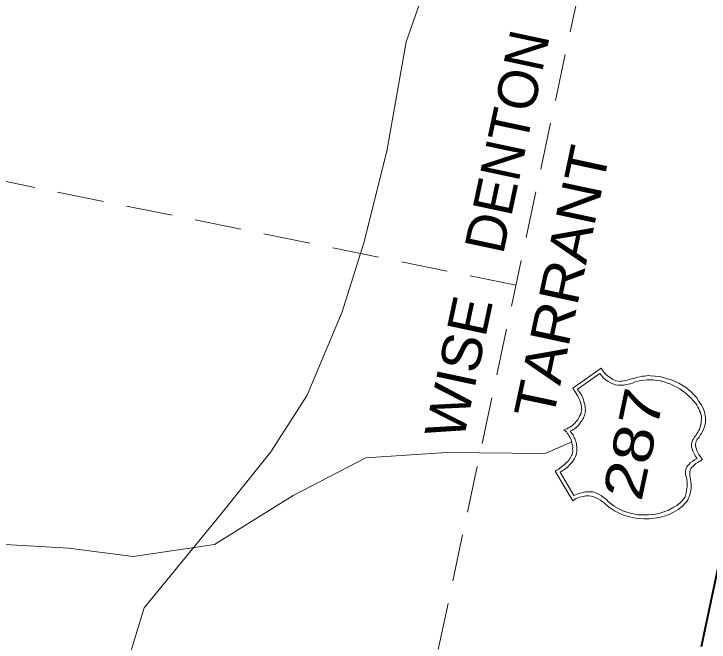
# Model space of a CAD drawing. Extents: x 2363411 to 2369126, y 6976878 to 6988319.
# Drawn here: x 2368067.8 to 2368157, y 6987951.6 to 6988032.2 of the extents above; entities that cross this region are included whole.
import ezdxf

# ---------------------------------------------------------------- set-up
doc = ezdxf.new("R2010")
doc.units = 0
doc.header["$LTSCALE"] = 2
doc.linetypes.add('LONG_DASHED', pattern=[7.5, 6, -1.5])
doc.linetypes.add('MEDIUM_DASHED', pattern=[4.5, 3, -1.5])
doc.layers.add('62', color=7, linetype='Continuous', lineweight=13)
doc.layers.add('63', color=7, linetype='Continuous', lineweight=13)

msp = doc.modelspace()

# ---------------------------------------------------------------- linework, layer by layer
at = {"layer": '62', "linetype": 'MEDIUM_DASHED'}
for p, q in [((2368191.192, 6988273.413), (2368097.525, 6987835.044)), ((2368132.221, 6987997.421), (2368039.262, 6988016.273))]:
    msp.add_line(p, q, dxfattribs=at)
at = {"layer": '62'}
msp.add_line((2368135.935, 6987975.828), (2368139.379, 6987977.301), dxfattribs=at)
for points in [[(2368072.165, 6987905.558), (2368069.558, 6987916.954), (2368070.74, 6987931.312), (2368081.321, 6987945.504), (2368084.53, 6987956.002), (2368094.219, 6987967.853), (2368100.778, 6987976.045), (2368105.415, 6987983.319), (2368109.901, 6987993.976), (2368112.685, 6988002.816), (2368115.664, 6988014.605), (2368118.107, 6988028.624), (2368124.138, 6988045.861), (2368127.394, 6988057.221), (2368131.763, 6988070.025), (2368141.291, 6988083.154), (2368150.678, 6988095.548), (2368159.881, 6988106.746), (2368173.939, 6988118.699), (2368182.972, 6988126.824), (2368192.837, 6988137.028), (2368200.988, 6988142.326)], [(2368139.487, 6987969.731), (2368137.22, 6987973.553), (2368137.457, 6987973.685), (2368137.692, 6987973.82), (2368137.889, 6987973.987), (2368138.097, 6987974.1), (2368138.269, 6987974.272), (2368138.441, 6987974.419), (2368138.611, 6987974.567), (2368138.785, 6987974.736), (2368138.929, 6987974.869), (2368139.037, 6987975.053), (2368139.161, 6987975.206), (2368139.248, 6987975.396), (2368139.352, 6987975.558), (2368139.428, 6987975.703), (2368139.475, 6987975.924), (2368139.496, 6987976.126), (2368139.502, 6987976.262), (2368139.469, 6987976.433), (2368139.486, 6987976.613), (2368139.48, 6987976.797), (2368139.427, 6987976.99), (2368139.395, 6987977.16), (2368139.344, 6987977.355), (2368139.294, 6987977.55), (2368139.195, 6987977.733), (2368139.123, 6987977.932), (2368139.004, 6987978.119), (2368138.925, 6987978.298), (2368138.794, 6987978.438), (2368138.67, 6987978.606), (2368138.506, 6987978.708), (2368138.353, 6987978.854), (2368138.552, 6987978.927), (2368138.754, 6987978.999), (2368138.956, 6987979.095), (2368139.117, 6987979.197), (2368139.326, 6987979.314), (2368139.473, 6987979.465), (2368139.64, 6987979.593), (2368139.787, 6987979.748), (2368139.912, 6987979.903), (2368140.057, 6987980.033), (2368140.168, 6987980.239), (2368140.266, 6987980.377), (2368140.362, 6987980.612), (2368140.463, 6987980.751), (2368140.552, 6987980.963), (2368140.589, 6987981.139), (2368140.624, 6987981.293), (2368140.667, 6987981.49), (2368140.627, 6987981.636), (2368140.626, 6987981.845), (2368140.575, 6987982.039), (2368140.543, 6987982.206), (2368140.465, 6987982.384), (2368140.398, 6987982.605), (2368140.32, 6987982.783), (2368140.226, 6987982.987), (2368140.128, 6987983.172), (2368140.015, 6987983.4), (2368139.894, 6987983.588), (2368139.777, 6987983.797), (2368139.634, 6987983.987), (2368139.496, 6987984.203), (2368143.127, 6987986.763), (2368143.353, 6987986.414), (2368143.621, 6987986.058), (2368143.952, 6987985.781), (2368144.292, 6987985.548), (2368144.634, 6987985.314), (2368144.972, 6987985.174), (2368145.258, 6987985.111), (2368145.456, 6987985.068), (2368145.62, 6987985.078), (2368145.833, 6987985.102), (2368146.022, 6987985.132), (2368146.262, 6987985.172), (2368146.506, 6987985.233), (2368146.747, 6987985.298), (2368147.018, 6987985.381), (2368147.309, 6987985.454), (2368147.582, 6987985.534), (2368147.852, 6987985.614), (2368148.16, 6987985.665), (2368148.426, 6987985.722), (2368148.709, 6987985.756), (2368148.969, 6987985.79), (2368149.227, 6987985.805), (2368149.477, 6987985.796), (2368150.063, 6987985.741), (2368150.628, 6987985.689), (2368151.135, 6987985.581), (2368151.65, 6987985.401), (2368152.149, 6987985.25), (2368152.634, 6987985.052), (2368153.09, 6987984.818), (2368153.541, 6987984.56), (2368153.972, 6987984.306), (2368154.364, 6987983.991)], [(2368154.885, 6987982.663), (2368154.685, 6987982.912), (2368154.437, 6987983.147), (2368154.168, 6987983.391), (2368153.873, 6987983.64), (2368153.554, 6987983.868), (2368153.213, 6987984.1), (2368152.845, 6987984.316), (2368152.471, 6987984.512), (2368152.056, 6987984.716), (2368151.624, 6987984.857), (2368151.198, 6987985.016), (2368150.715, 6987985.119), (2368150.246, 6987985.194), (2368149.798, 6987985.245), (2368149.414, 6987985.28), (2368149.037, 6987985.246), (2368148.689, 6987985.228), (2368148.354, 6987985.163), (2368148.021, 6987985.118), (2368147.729, 6987985.043), (2368147.432, 6987984.945), (2368147.135, 6987984.847), (2368146.867, 6987984.769), (2368146.598, 6987984.71), (2368146.333, 6987984.65), (2368146.066, 6987984.592), (2368145.811, 6987984.577), (2368145.577, 6987984.56), (2368145.304, 6987984.571), (2368144.971, 6987984.62), (2368144.653, 6987984.757), (2368144.337, 6987984.894), (2368144.026, 6987985.051), (2368143.726, 6987985.254), (2368143.454, 6987985.498), (2368143.213, 6987985.777), (2368142.976, 6987986.058), (2368140.107, 6987984.048), (2368140.231, 6987983.862), (2368140.354, 6987983.694), (2368140.498, 6987983.504), (2368140.598, 6987983.323), (2368140.692, 6987983.119), (2368140.787, 6987982.915), (2368140.858, 6987982.715), (2368140.932, 6987982.515), (2368140.977, 6987982.299), (2368141.048, 6987982.098), (2368141.072, 6987981.886), (2368141.101, 6987981.694), (2368141.107, 6987981.511), (2368141.097, 6987981.351), (2368141.108, 6987981.189), (2368141.075, 6987981.037), (2368141.042, 6987980.88), (2368140.982, 6987980.709), (2368140.917, 6987980.516), (2368140.864, 6987980.366), (2368140.749, 6987980.162), (2368140.651, 6987980.021), (2368140.548, 6987979.861), (2368140.417, 6987979.68), (2368140.297, 6987979.546), (2368140.167, 6987979.366), (2368140.027, 6987979.257), (2368139.884, 6987979.128), (2368139.715, 6987978.978), (2368139.532, 6987978.878), (2368139.372, 6987978.775), (2368139.144, 6987978.686), (2368139.295, 6987978.515), (2368139.419, 6987978.352), (2368139.524, 6987978.19), (2368139.605, 6987978.036), (2368139.66, 6987977.862), (2368139.745, 6987977.73), (2368139.821, 6987977.532), (2368139.9, 6987977.373), (2368139.914, 6987977.211), (2368139.964, 6987977.016), (2368139.978, 6987976.874), (2368140.008, 6987976.684), (2368139.995, 6987976.525), (2368140.03, 6987976.358), (2368140.013, 6987976.177), (2368140.004, 6987976.018), (2368139.993, 6987975.861), (2368139.946, 6987975.64), (2368139.858, 6987975.452), (2368139.767, 6987975.242), (2368139.663, 6987975.078), (2368139.529, 6987974.876), (2368139.394, 6987974.674), (2368139.251, 6987974.547), (2368139.095, 6987974.349), (2368138.941, 6987974.175), (2368138.771, 6987974.026), (2368138.586, 6987973.906), (2368138.411, 6987973.734), (2368138.202, 6987973.62)], [(2368154.364, 6987983.991), (2368154.73, 6987983.662), (2368155.065, 6987983.291), (2368155.404, 6987982.941), (2368155.677, 6987982.494), (2368155.959, 6987982.088), (2368156.203, 6987981.621), (2368156.311, 6987981.369), (2368156.4, 6987981.141), (2368156.441, 6987980.903), (2368156.483, 6987980.665), (2368156.529, 6987980.449), (2368156.527, 6987980.218), (2368156.517, 6987979.967), (2368156.499, 6987979.766), (2368156.469, 6987979.517), (2368156.398, 6987979.301), (2368156.334, 6987979.108), (2368156.274, 6987978.937), (2368156.163, 6987978.733), (2368156.101, 6987978.56), (2368155.999, 6987978.396), (2368155.873, 6987978.241), (2368155.791, 6987978.075), (2368155.687, 6987977.913), (2368155.57, 6987977.799), (2368155.467, 6987977.637), (2368155.417, 6987977.512), (2368155.337, 6987977.343), (2368155.276, 6987977.17), (2368155.244, 6987977.019), (2368155.249, 6987976.832), (2368155.274, 6987976.621), (2368155.346, 6987976.423), (2368155.413, 6987976.2), (2368155.542, 6987975.944), (2368155.673, 6987975.684), (2368155.882, 6987975.386), (2368156.114, 6987975.063), (2368155.793, 6987974.853), (2368155.526, 6987974.681), (2368155.264, 6987974.528), (2368155.084, 6987974.338), (2368154.919, 6987974.209), (2368154.771, 6987974.059), (2368154.673, 6987973.918), (2368154.598, 6987973.773), (2368154.546, 6987973.647), (2368154.514, 6987973.492), (2368154.507, 6987973.357), (2368154.519, 6987973.193), (2368154.517, 6987973.079), (2368154.527, 6987972.917), (2368154.56, 6987972.746), (2368154.577, 6987972.605), (2368154.613, 6987972.459), (2368154.625, 6987972.295), (2368154.654, 6987972.104), (2368154.677, 6987971.895), (2368154.662, 6987971.714), (2368154.664, 6987971.507), (2368154.665, 6987971.296), (2368154.649, 6987971.115), (2368154.603, 6987970.898), (2368154.56, 6987970.699), (2368154.518, 6987970.501), (2368154.444, 6987970.262), (2368154.336, 6987970.08), (2368154.246, 6987969.868), (2368154.108, 6987969.664), (2368153.954, 6987969.468), (2368153.514, 6987969.035), (2368152.993, 6987968.639), (2368152.433, 6987968.276), (2368151.846, 6987968.011), (2368151.22, 6987967.776), (2368150.609, 6987967.606), (2368149.948, 6987967.52), (2368149.267, 6987967.457), (2368148.595, 6987967.439), (2368147.959, 6987967.483), (2368147.29, 6987967.579), (2368146.651, 6987967.716), (2368146.004, 6987967.924), (2368145.432, 6987968.16), (2368144.833, 6987968.472), (2368144.331, 6987968.813), (2368144.128, 6987968.946), (2368143.931, 6987969.103), (2368143.718, 6987969.287), (2368143.506, 6987969.47), (2368143.268, 6987969.659), (2368143.034, 6987969.848), (2368142.77, 6987970.017), (2368142.497, 6987970.145), (2368142.204, 6987970.279), (2368141.875, 6987970.348), (2368141.562, 6987970.392), (2368141.191, 6987970.379), (2368140.81, 6987970.32), (2368140.371, 6987970.209)], [(2368137.859, 6987973.415), (2368139.634, 6987970.411), (2368140.041, 6987970.6), (2368140.462, 6987970.742), (2368140.826, 6987970.826), (2368141.167, 6987970.912), (2368141.489, 6987970.913), (2368141.812, 6987970.913), (2368142.079, 6987970.879), (2368142.361, 6987970.796), (2368142.634, 6987970.668), (2368142.889, 6987970.569), (2368143.154, 6987970.42), (2368143.39, 6987970.233), (2368143.609, 6987970.069), (2368143.845, 6987969.882), (2368144.054, 6987969.676), (2368144.286, 6987969.465), (2368144.796, 6987969.057), (2368145.391, 6987968.721), (2368145.931, 6987968.446), (2368146.577, 6987968.241), (2368147.234, 6987968.076), (2368147.877, 6987967.961), (2368148.563, 6987967.929), (2368149.206, 6987967.931), (2368149.886, 6987967.992), (2368150.539, 6987968.128), (2368151.175, 6987968.316), (2368151.773, 6987968.529), (2368152.298, 6987968.834), (2368152.827, 6987969.157), (2368153.301, 6987969.541), (2368153.707, 6987969.938), (2368153.754, 6987970.043), (2368153.848, 6987970.162), (2368153.902, 6987970.31), (2368153.94, 6987970.486), (2368153.99, 6987970.614), (2368154.051, 6987970.785), (2368154.089, 6987970.961), (2368154.103, 6987971.14), (2368154.123, 6987971.345), (2368154.157, 6987971.499), (2368154.156, 6987971.706), (2368154.17, 6987971.887), (2368154.181, 6987972.046), (2368154.154, 6987972.236), (2368154.142, 6987972.398), (2368154.126, 6987972.542), (2368154.066, 6987972.69), (2368154.034, 6987972.859), (2368153.991, 6987972.984), (2368153.957, 6987973.151), (2368153.947, 6987973.315), (2368153.952, 6987973.451), (2368153.963, 6987973.61), (2368153.996, 6987973.765), (2368154.052, 6987973.914), (2368154.136, 6987974.103), (2368154.24, 6987974.264), (2368154.41, 6987974.412), (2368154.568, 6987974.607), (2368154.836, 6987974.781), (2368155.112, 6987974.999), (2368155.45, 6987975.18), (2368155.202, 6987975.531), (2368155.04, 6987975.842), (2368154.893, 6987976.127), (2368154.791, 6987976.401), (2368154.744, 6987976.619), (2368154.719, 6987976.831), (2368154.714, 6987977.016), (2368154.761, 6987977.235), (2368154.817, 6987977.385), (2368154.87, 6987977.537), (2368154.98, 6987977.718), (2368155.083, 6987977.88), (2368155.181, 6987978.021), (2368155.308, 6987978.18), (2368155.416, 6987978.361), (2368155.547, 6987978.54), (2368155.633, 6987978.73), (2368155.74, 6987978.914), (2368155.805, 6987979.106), (2368155.873, 6987979.323), (2368155.939, 6987979.515), (2368155.962, 6987979.739), (2368155.984, 6987979.944), (2368156.008, 6987980.167), (2368155.99, 6987980.402), (2368155.989, 6987980.609), (2368155.903, 6987980.857), (2368155.857, 6987981.075), (2368155.766, 6987981.301), (2368155.682, 6987981.548), (2368155.544, 6987981.762), (2368155.411, 6987981.998), (2368155.273, 6987982.212), (2368155.067, 6987982.44), (2368154.885, 6987982.663)], [(2368025.714, 6987952.874), (2368032.817, 6987957.042), (2368045.955, 6987961.554), (2368060.031, 6987964.547), (2368074.826, 6987963.689), (2368083.09, 6987962.614), (2368093.559, 6987964.126), (2368103.628, 6987970.442), (2368112.944, 6987975.264), (2368123.278, 6987975.931), (2368135.935, 6987975.828)], [(2368138.202, 6987973.62), (2368138.019, 6987973.52), (2368137.859, 6987973.415)], [(2368140.371, 6987970.209), (2368139.941, 6987970.025), (2368139.487, 6987969.731)]]:
    msp.add_lwpolyline(points, dxfattribs=at)
at = {"layer": '62', "linetype": 'LONG_DASHED', "lineweight": 40}
msp.add_lwpolyline([(2368131.526, 6987836.733), (2368193.933, 6987823.396), (2368230.26, 6987993.411), (2368167.854, 6988006.745), (2368131.46, 6987836.424)], dxfattribs=at)
at = {"layer": '63', "linetype": 'MEDIUM_DASHED'}
for p, q in [((2368191.192, 6988273.413), (2368097.525, 6987835.044)), ((2368132.221, 6987997.421), (2368039.262, 6988016.273))]:
    msp.add_line(p, q, dxfattribs=at)
at = {"layer": '63'}
msp.add_line((2368135.935, 6987975.828), (2368139.379, 6987977.301), dxfattribs=at)
for points in [[(2368072.165, 6987905.558), (2368069.558, 6987916.954), (2368070.74, 6987931.312), (2368081.321, 6987945.504), (2368084.53, 6987956.002), (2368094.219, 6987967.853), (2368100.778, 6987976.045), (2368105.415, 6987983.319), (2368109.901, 6987993.976), (2368112.685, 6988002.816), (2368115.664, 6988014.605), (2368118.107, 6988028.624), (2368124.138, 6988045.861), (2368127.394, 6988057.221), (2368131.763, 6988070.025), (2368141.291, 6988083.154), (2368150.678, 6988095.548), (2368159.881, 6988106.746), (2368173.939, 6988118.699), (2368182.972, 6988126.824), (2368192.837, 6988137.028), (2368200.988, 6988142.326)], [(2368139.487, 6987969.731), (2368137.22, 6987973.553), (2368137.457, 6987973.685), (2368137.692, 6987973.82), (2368137.889, 6987973.987), (2368138.097, 6987974.1), (2368138.269, 6987974.272), (2368138.441, 6987974.419), (2368138.611, 6987974.567), (2368138.785, 6987974.736), (2368138.929, 6987974.869), (2368139.037, 6987975.053), (2368139.161, 6987975.206), (2368139.248, 6987975.396), (2368139.352, 6987975.558), (2368139.428, 6987975.703), (2368139.475, 6987975.924), (2368139.496, 6987976.126), (2368139.502, 6987976.262), (2368139.469, 6987976.433), (2368139.486, 6987976.613), (2368139.48, 6987976.797), (2368139.427, 6987976.99), (2368139.395, 6987977.16), (2368139.344, 6987977.355), (2368139.294, 6987977.55), (2368139.195, 6987977.733), (2368139.123, 6987977.932), (2368139.004, 6987978.119), (2368138.925, 6987978.298), (2368138.794, 6987978.438), (2368138.67, 6987978.606), (2368138.506, 6987978.708), (2368138.353, 6987978.854), (2368138.552, 6987978.927), (2368138.754, 6987978.999), (2368138.956, 6987979.095), (2368139.117, 6987979.197), (2368139.326, 6987979.314), (2368139.473, 6987979.465), (2368139.64, 6987979.593), (2368139.787, 6987979.748), (2368139.912, 6987979.903), (2368140.057, 6987980.033), (2368140.168, 6987980.239), (2368140.266, 6987980.377), (2368140.362, 6987980.612), (2368140.463, 6987980.751), (2368140.552, 6987980.963), (2368140.589, 6987981.139), (2368140.624, 6987981.293), (2368140.667, 6987981.49), (2368140.627, 6987981.636), (2368140.626, 6987981.845), (2368140.575, 6987982.039), (2368140.543, 6987982.206), (2368140.465, 6987982.384), (2368140.398, 6987982.605), (2368140.32, 6987982.783), (2368140.226, 6987982.987), (2368140.128, 6987983.172), (2368140.015, 6987983.4), (2368139.894, 6987983.588), (2368139.777, 6987983.797), (2368139.634, 6987983.987), (2368139.496, 6987984.203), (2368143.127, 6987986.763), (2368143.353, 6987986.414), (2368143.621, 6987986.058), (2368143.952, 6987985.781), (2368144.292, 6987985.548), (2368144.634, 6987985.314), (2368144.972, 6987985.174), (2368145.258, 6987985.111), (2368145.456, 6987985.068), (2368145.62, 6987985.078), (2368145.833, 6987985.102), (2368146.022, 6987985.132), (2368146.262, 6987985.172), (2368146.506, 6987985.233), (2368146.747, 6987985.298), (2368147.018, 6987985.381), (2368147.309, 6987985.454), (2368147.582, 6987985.534), (2368147.852, 6987985.614), (2368148.16, 6987985.665), (2368148.426, 6987985.722), (2368148.709, 6987985.756), (2368148.969, 6987985.79), (2368149.227, 6987985.805), (2368149.477, 6987985.796), (2368150.063, 6987985.741), (2368150.628, 6987985.689), (2368151.135, 6987985.581), (2368151.65, 6987985.401), (2368152.149, 6987985.25), (2368152.634, 6987985.052), (2368153.09, 6987984.818), (2368153.541, 6987984.56), (2368153.972, 6987984.306), (2368154.364, 6987983.991)], [(2368154.885, 6987982.663), (2368154.685, 6987982.912), (2368154.437, 6987983.147), (2368154.168, 6987983.391), (2368153.873, 6987983.64), (2368153.554, 6987983.868), (2368153.213, 6987984.1), (2368152.845, 6987984.316), (2368152.471, 6987984.512), (2368152.056, 6987984.716), (2368151.624, 6987984.857), (2368151.198, 6987985.016), (2368150.715, 6987985.119), (2368150.246, 6987985.194), (2368149.798, 6987985.245), (2368149.414, 6987985.28), (2368149.037, 6987985.246), (2368148.689, 6987985.228), (2368148.354, 6987985.163), (2368148.021, 6987985.118), (2368147.729, 6987985.043), (2368147.432, 6987984.945), (2368147.135, 6987984.847), (2368146.867, 6987984.769), (2368146.598, 6987984.71), (2368146.333, 6987984.65), (2368146.066, 6987984.592), (2368145.811, 6987984.577), (2368145.577, 6987984.56), (2368145.304, 6987984.571), (2368144.971, 6987984.62), (2368144.653, 6987984.757), (2368144.337, 6987984.894), (2368144.026, 6987985.051), (2368143.726, 6987985.254), (2368143.454, 6987985.498), (2368143.213, 6987985.777), (2368142.976, 6987986.058), (2368140.107, 6987984.048), (2368140.231, 6987983.862), (2368140.354, 6987983.694), (2368140.498, 6987983.504), (2368140.598, 6987983.323), (2368140.692, 6987983.119), (2368140.787, 6987982.915), (2368140.858, 6987982.715), (2368140.932, 6987982.515), (2368140.977, 6987982.299), (2368141.048, 6987982.098), (2368141.072, 6987981.886), (2368141.101, 6987981.694), (2368141.107, 6987981.511), (2368141.097, 6987981.351), (2368141.108, 6987981.189), (2368141.075, 6987981.037), (2368141.042, 6987980.88), (2368140.982, 6987980.709), (2368140.917, 6987980.516), (2368140.864, 6987980.366), (2368140.749, 6987980.162), (2368140.651, 6987980.021), (2368140.548, 6987979.861), (2368140.417, 6987979.68), (2368140.297, 6987979.546), (2368140.167, 6987979.366), (2368140.027, 6987979.257), (2368139.884, 6987979.128), (2368139.715, 6987978.978), (2368139.532, 6987978.878), (2368139.372, 6987978.775), (2368139.144, 6987978.686), (2368139.295, 6987978.515), (2368139.419, 6987978.352), (2368139.524, 6987978.19), (2368139.605, 6987978.036), (2368139.66, 6987977.862), (2368139.745, 6987977.73), (2368139.821, 6987977.532), (2368139.9, 6987977.373), (2368139.914, 6987977.211), (2368139.964, 6987977.016), (2368139.978, 6987976.874), (2368140.008, 6987976.684), (2368139.995, 6987976.525), (2368140.03, 6987976.358), (2368140.013, 6987976.177), (2368140.004, 6987976.018), (2368139.993, 6987975.861), (2368139.946, 6987975.64), (2368139.858, 6987975.452), (2368139.767, 6987975.242), (2368139.663, 6987975.078), (2368139.529, 6987974.876), (2368139.394, 6987974.674), (2368139.251, 6987974.547), (2368139.095, 6987974.349), (2368138.941, 6987974.175), (2368138.771, 6987974.026), (2368138.586, 6987973.906), (2368138.411, 6987973.734), (2368138.202, 6987973.62)], [(2368154.364, 6987983.991), (2368154.73, 6987983.662), (2368155.065, 6987983.291), (2368155.404, 6987982.941), (2368155.677, 6987982.494), (2368155.959, 6987982.088), (2368156.203, 6987981.621), (2368156.311, 6987981.369), (2368156.4, 6987981.141), (2368156.441, 6987980.903), (2368156.483, 6987980.665), (2368156.529, 6987980.449), (2368156.527, 6987980.218), (2368156.517, 6987979.967), (2368156.499, 6987979.766), (2368156.469, 6987979.517), (2368156.398, 6987979.301), (2368156.334, 6987979.108), (2368156.274, 6987978.937), (2368156.163, 6987978.733), (2368156.101, 6987978.56), (2368155.999, 6987978.396), (2368155.873, 6987978.241), (2368155.791, 6987978.075), (2368155.687, 6987977.913), (2368155.57, 6987977.799), (2368155.467, 6987977.637), (2368155.417, 6987977.512), (2368155.337, 6987977.343), (2368155.276, 6987977.17), (2368155.244, 6987977.019), (2368155.249, 6987976.832), (2368155.274, 6987976.621), (2368155.346, 6987976.423), (2368155.413, 6987976.2), (2368155.542, 6987975.944), (2368155.673, 6987975.684), (2368155.882, 6987975.386), (2368156.114, 6987975.063), (2368155.793, 6987974.853), (2368155.526, 6987974.681), (2368155.264, 6987974.528), (2368155.084, 6987974.338), (2368154.919, 6987974.209), (2368154.771, 6987974.059), (2368154.673, 6987973.918), (2368154.598, 6987973.773), (2368154.546, 6987973.647), (2368154.514, 6987973.492), (2368154.507, 6987973.357), (2368154.519, 6987973.193), (2368154.517, 6987973.079), (2368154.527, 6987972.917), (2368154.56, 6987972.746), (2368154.577, 6987972.605), (2368154.613, 6987972.459), (2368154.625, 6987972.295), (2368154.654, 6987972.104), (2368154.677, 6987971.895), (2368154.662, 6987971.714), (2368154.664, 6987971.507), (2368154.665, 6987971.296), (2368154.649, 6987971.115), (2368154.603, 6987970.898), (2368154.56, 6987970.699), (2368154.518, 6987970.501), (2368154.444, 6987970.262), (2368154.336, 6987970.08), (2368154.246, 6987969.868), (2368154.108, 6987969.664), (2368153.954, 6987969.468), (2368153.514, 6987969.035), (2368152.993, 6987968.639), (2368152.433, 6987968.276), (2368151.846, 6987968.011), (2368151.22, 6987967.776), (2368150.609, 6987967.606), (2368149.948, 6987967.52), (2368149.267, 6987967.457), (2368148.595, 6987967.439), (2368147.959, 6987967.483), (2368147.29, 6987967.579), (2368146.651, 6987967.716), (2368146.004, 6987967.924), (2368145.432, 6987968.16), (2368144.833, 6987968.472), (2368144.331, 6987968.813), (2368144.128, 6987968.946), (2368143.931, 6987969.103), (2368143.718, 6987969.287), (2368143.506, 6987969.47), (2368143.268, 6987969.659), (2368143.034, 6987969.848), (2368142.77, 6987970.017), (2368142.497, 6987970.145), (2368142.204, 6987970.279), (2368141.875, 6987970.348), (2368141.562, 6987970.392), (2368141.191, 6987970.379), (2368140.81, 6987970.32), (2368140.371, 6987970.209)], [(2368137.859, 6987973.415), (2368139.634, 6987970.411), (2368140.041, 6987970.6), (2368140.462, 6987970.742), (2368140.826, 6987970.826), (2368141.167, 6987970.912), (2368141.489, 6987970.913), (2368141.812, 6987970.913), (2368142.079, 6987970.879), (2368142.361, 6987970.796), (2368142.634, 6987970.668), (2368142.889, 6987970.569), (2368143.154, 6987970.42), (2368143.39, 6987970.233), (2368143.609, 6987970.069), (2368143.845, 6987969.882), (2368144.054, 6987969.676), (2368144.286, 6987969.465), (2368144.796, 6987969.057), (2368145.391, 6987968.721), (2368145.931, 6987968.446), (2368146.577, 6987968.241), (2368147.234, 6987968.076), (2368147.877, 6987967.961), (2368148.563, 6987967.929), (2368149.206, 6987967.931), (2368149.886, 6987967.992), (2368150.539, 6987968.128), (2368151.175, 6987968.316), (2368151.773, 6987968.529), (2368152.298, 6987968.834), (2368152.827, 6987969.157), (2368153.301, 6987969.541), (2368153.707, 6987969.938), (2368153.754, 6987970.043), (2368153.848, 6987970.162), (2368153.902, 6987970.31), (2368153.94, 6987970.486), (2368153.99, 6987970.614), (2368154.051, 6987970.785), (2368154.089, 6987970.961), (2368154.103, 6987971.14), (2368154.123, 6987971.345), (2368154.157, 6987971.499), (2368154.156, 6987971.706), (2368154.17, 6987971.887), (2368154.181, 6987972.046), (2368154.154, 6987972.236), (2368154.142, 6987972.398), (2368154.126, 6987972.542), (2368154.066, 6987972.69), (2368154.034, 6987972.859), (2368153.991, 6987972.984), (2368153.957, 6987973.151), (2368153.947, 6987973.315), (2368153.952, 6987973.451), (2368153.963, 6987973.61), (2368153.996, 6987973.765), (2368154.052, 6987973.914), (2368154.136, 6987974.103), (2368154.24, 6987974.264), (2368154.41, 6987974.412), (2368154.568, 6987974.607), (2368154.836, 6987974.781), (2368155.112, 6987974.999), (2368155.45, 6987975.18), (2368155.202, 6987975.531), (2368155.04, 6987975.842), (2368154.893, 6987976.127), (2368154.791, 6987976.401), (2368154.744, 6987976.619), (2368154.719, 6987976.831), (2368154.714, 6987977.016), (2368154.761, 6987977.235), (2368154.817, 6987977.385), (2368154.87, 6987977.537), (2368154.98, 6987977.718), (2368155.083, 6987977.88), (2368155.181, 6987978.021), (2368155.308, 6987978.18), (2368155.416, 6987978.361), (2368155.547, 6987978.54), (2368155.633, 6987978.73), (2368155.74, 6987978.914), (2368155.805, 6987979.106), (2368155.873, 6987979.323), (2368155.939, 6987979.515), (2368155.962, 6987979.739), (2368155.984, 6987979.944), (2368156.008, 6987980.167), (2368155.99, 6987980.402), (2368155.989, 6987980.609), (2368155.903, 6987980.857), (2368155.857, 6987981.075), (2368155.766, 6987981.301), (2368155.682, 6987981.548), (2368155.544, 6987981.762), (2368155.411, 6987981.998), (2368155.273, 6987982.212), (2368155.067, 6987982.44), (2368154.885, 6987982.663)], [(2368025.714, 6987952.874), (2368032.817, 6987957.042), (2368045.955, 6987961.554), (2368060.031, 6987964.547), (2368074.826, 6987963.689), (2368083.09, 6987962.614), (2368093.559, 6987964.126), (2368103.628, 6987970.442), (2368112.944, 6987975.264), (2368123.278, 6987975.931), (2368135.935, 6987975.828)], [(2368138.202, 6987973.62), (2368138.019, 6987973.52), (2368137.859, 6987973.415)], [(2368140.371, 6987970.209), (2368139.941, 6987970.025), (2368139.487, 6987969.731)]]:
    msp.add_lwpolyline(points, dxfattribs=at)
at = {"layer": '63', "linetype": 'LONG_DASHED', "lineweight": 40}
msp.add_lwpolyline([(2368131.526, 6987836.733), (2368193.933, 6987823.396), (2368230.26, 6987993.411), (2368167.854, 6988006.745), (2368131.46, 6987836.424)], dxfattribs=at)

# ---------------------------------------------------------------- texts
at = {"layer": '62'}
msp.add_text('DENTON', height=5.099, rotation=77.939, dxfattribs=at).set_placement((2368130.55, 6988001.233))
for s, height, width, p in [('TARRANT', 5.099, 1.1, (2368136.909, 6987979.946)), ('PROJECT', 23.83, 1.1, (2368162.459, 6987834.611)), ('WISE', 5.099, 1.05, (2368125.448, 6987977.358)), ('287', 5.099, 1.25, (2368148.281, 6987969.532))]:
    msp.add_text(s, height=height, rotation=77.939, dxfattribs=dict(at, width=width)).set_placement(p)
at = {"layer": '63'}
msp.add_text('DENTON', height=5.099, rotation=77.939, dxfattribs=at).set_placement((2368130.55, 6988001.233))
for s, height, width, p in [('TARRANT', 5.099, 1.1, (2368136.909, 6987979.946)), ('PROJECT', 23.83, 1.1, (2368162.459, 6987834.611)), ('WISE', 5.099, 1.05, (2368125.448, 6987977.358)), ('287', 5.099, 1.25, (2368148.281, 6987969.532))]:
    msp.add_text(s, height=height, rotation=77.939, dxfattribs=dict(at, width=width)).set_placement(p)

doc.saveas('drawing.dxf')
